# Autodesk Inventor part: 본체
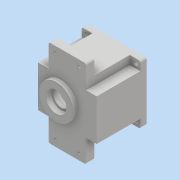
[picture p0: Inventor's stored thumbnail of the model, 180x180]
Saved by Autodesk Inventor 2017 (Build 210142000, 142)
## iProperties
Part Number: 본체
Material: 일반
Document SubType Name: Modeling
Designer: user
Density: 1 g/cm^3
Appearance: 기본값
Mass: 324.576 g
Surface Area: 793.925 cm^2
Volume: 324.576 cm^3
Author: user
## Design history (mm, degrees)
sketch "스케치1"
  geometry: L1 (-30, 70)-(30, 70); L2 (30, -70)-(-30, -70); L3 (-30, 70)-(30, -70); L4 (30, 70)-(-30, -70); L5 (47, 33)-(47, -33); L6 (-47, -33)-(-47, 33); L7 (-47, 33)-(47, -33); L8 (47, 33)-(-47, -33); L9 (30, 70)-(30, 33); L10 (30, -33)-(30, -70); L11 (-47, 33)-(-30, 33); L12 (30, 33)-(47, 33); L13 (-30, -70)-(-30, -33); L14 (-30, 33)-(-30, 70); L15 (47, -33)-(30, -33); L16 (-30, -33)-(-47, -33); 1 further point
  constraints: 32 end point, 10 parallel, 4 midpoint, 4 perpendicular, 3 horizontal
  dimensions: "d6" = 60 distance of L2.start L2.end; "d7" = 140 distance of L1.end L2.start; "d8" = 94 distance of L5.end L6.start; "d9" = 66 distance of L5.start L5.end; "d10" = 60 distance of L1.start L1.end; "d11" = 66 distance of L6.start L6.end; "d12" = 37 distance of L11.end L1.start; "d13" = 37 distance of L2.end L13.end
extrude "돌출1" new body sketch "스케치1" distance "d14" = 13; taper "d15" = 0 deg
sketch "스케치2"
  geometry: L1 (-30, 33)-(-30, 70) reference; L2 (30, -33)-(47, -33) reference; L3 (47, 33)-(47, -33); L4 (-47, -33)-(-47, 33); L5 (-47, 33)-(47, -33); L6 (47, 33)-(-47, -33); L7 (30, -70)-(30, -33) reference; L8 (-30, 47)-(30, 47); L9 (30, -47)-(-30, -47); L10 (-30, 47)-(30, -47); L11 (30, 47)-(-30, -47); L12 (30, 47)-(30, 33); L13 (30, -33)-(30, -47); L14 (-47, 33)-(-30, 33); L15 (30, 33)-(47, 33); L16 (47, -33)-(30, -33); L17 (-30, -33)-(-47, -33); L18 (-30, -47)-(-30, -33); L19 (-30, 33)-(-30, 47); 1 further point
  constraints: 32 end point, 10 parallel, 4 midpoint, 4 perpendicular, 3 horizontal, 1 point on line
  dimensions: "d31" = 94 distance of L8.end L9.start; "d32" = 60 distance of L8.start L8.end; "d33" = 66 distance of L4.start L4.end; "d34" = 60 distance of L9.start L9.end; "d35" = 17 distance of L4.end L14.end
extrude "돌출2" join sketch "스케치2" distance "d16" = 57; taper "d17" = 0 deg
sketch "스케치3"
  geometry: L1 (47, -47)-(-47, -47); L2 (-47, -47)-(-47, 47); L3 (-47, 47)-(47, 47); L4 (47, 47)-(47, -47); L5 (47, -47)-(-47, 47); L6 (-47, -47)-(47, 47); 1 further point
  constraints: 12 end point, 2 midpoint, 2 parallel, 1 horizontal, 1 perpendicular
  dimensions: "d18" = 94 distance of L2.end L3.end; "d19" = 94 distance of L1.end L2.end
extrude "돌출3" join sketch "스케치3" distance "d20" = 10; taper "d21" = 0 deg
sketch "스케치4"
  geometry: C1 r 43 at (0, 0); 1 further point
  constraints: 1 centre point, 1 coincident
  dimensions: "d22" = 86 diameter of C1
extrude "돌출4" cut sketch "스케치4" distance "d23" = 9; taper "d24" = 0 deg
sketch "스케치5"
  geometry: C1 r 40 at (0, 0); 1 further point
  constraints: 1 centre point, 1 coincident
  dimensions: "d30" = 80 diameter of C1
extrude "돌출5" cut sketch "스케치5" distance "d36" = 62; taper "d37" = 0 deg
sketch "스케치6"
  geometry: L1 (3.994, -35.778)-(3.994, -39.8); L2 (3.994, -35.778)-(8.016, -35.778); L3 (-3.994, -35.778)-(-3.994, -39.8); L4 (-3.994, -35.778)-(0.029, -35.778); L5 (-3.994, 35.778)-(-3.994, 36.333); L6 (-3.994, 35.778)-(-3.439, 35.778); L7 (3.994, 35.778)-(3.994, 36.333); L8 (3.994, 35.778)-(4.549, 35.778); A1 r 36 centre (0, 0) between (0, -36) and (0, 36); A2 r 4 centre (0, -36) between (3.994, -35.778) and (-3.994, -35.778); A3 r 4 centre (0, 36) between (-3.994, 36.222) and (3.994, 36.222); A4 r 40 centre (0, 0) between (-3.994, 39.8) and (3.994, 39.8) reference; A5 r 40 centre (0, 0) between (-7.561, 39.279) and (7.561, 39.279); A6 r 3 centre (-6.994, 36.333) between (-3.994, 36.333) and (-7.561, 39.279); A7 r 3 centre (6.994, 36.333) between (7.561, 39.279) and (3.994, 36.333); 1 further point
  constraints: 24 point on circle, 16 end point, 6 centre point, 4 horizontal, 4 perpendicular, 4 point on line, 4 tangent, 2 coincident, 2 equal radius, 2 vertical alignment
  dimensions: "d38" = 72 diameter of A1; "d95" = 8 diameter of A3; "d96" = 8 diameter of A2; "d97" = 90 deg angle of L1 L2; "d98" = 90 deg angle of L3 L4; "d99" = 90 deg angle of L6 L5; "d100" = 90 deg angle of L8 L7; "d101" = 3 radius of A6 (derived)
sketch "스케치14"
  geometry: L1 (0, 0)-(-11, 0); L2 (0, 0)-(20, 0); A1 r 21 centre (-11, 0) between (7.984, 8.978) and (7.984, -8.978); A2 r 15 centre (20, 0) between (7.984, -8.978) and (7.984, 8.978)
  constraints: 4 end point, 4 point on circle, 2 centre point, 2 coincident, 2 horizontal
  dimensions: "d60" = 11 distance of L1.start L1.end; "d62" = 20 distance of L1.start L2.end; "d63" = 42 diameter of A1; "d64" = 30 diameter of A2
extrude "돌출12" join sketch "스케치14" distance "d65" = 7; taper "d66" = 0 deg
sketch "스케치15"
  geometry: C1 r 17.5 at (-11, 0); A1 r 21 centre (-11, 0) between (7.984, 8.978) and (7.984, -8.978) reference; 1 further point
  constraints: 1 centre point, 1 coincident
  dimensions: "d67" = 35 diameter of C1
extrude "돌출13" cut sketch "스케치15" distance "d68" = 10; taper "d69" = 0 deg
sketch "스케치16"
  geometry: C1 r 17.5 at (0, 0) reference; C2 r 12.5 at (0, 0); 1 further point
  constraints: 1 centre point, 1 coincident
  dimensions: "d70" = 25 diameter of C2
extrude "돌출14" cut sketch "스케치16" distance "d71" = 4.7; taper "d72" = 0 deg
sketch "스케치18"
  geometry: C1 r 27.5 at (-11, 0); 2 further points
  constraints: 1 centre point, 1 coincident
  dimensions: "d73" = 55 diameter of C1
extrude "돌출15" join sketch "스케치18" distance "d74" = 7; taper "d75" = 0 deg
sketch "스케치19"
  geometry: C1 r 27.5 at (0, 0) reference; C2 r 16 at (0, 0); 1 further point
  constraints: 1 centre point, 1 coincident
  dimensions: "d76" = 32 diameter of C2
extrude "돌출16" cut sketch "스케치19" distance "d77" = 8.3; taper "d78" = 0 deg
sketch "스케치20"
  geometry: C1 r 11 at (20, 0); A1 r 15 centre (20, 0) between (7.984, -8.978) and (7.984, 8.978) reference; 1 further point
  constraints: 1 centre point, 1 coincident
  dimensions: "d79" = 22 diameter of C1
extrude "돌출17" cut sketch "스케치20" distance "d80" = 7; taper "d81" = 0 deg
sketch "스케치21"
  geometry: C1 r 11 at (0, 0) reference; C2 r 9.5 at (0, 0); 1 further point
  constraints: 1 centre point, 1 coincident
  dimensions: "d82" = 19 diameter of C2
extrude "돌출18" cut sketch "스케치21" distance "d83" = 3; taper "d84" = 0 deg
chamfer "모따기1" distance "d86" = 1; stored, may be unused: second distance "d87" = 2, angle "d88" = 45 deg
chamfer "모따기2" distance "d89" = 0.8; stored, may be unused: second distance "d90" = 2, angle "d91" = 30 deg
chamfer "모따기3" distance "d92" = 1; stored, may be unused: second distance "d93" = 2, angle "d94" = 45 deg
extrude "돌출19" join sketch "스케치6" distance "d102" = 62; taper "d103" = 0 deg
sketch "스케치22"
  geometry: A1 r 4 centre (0, -36) between (3.994, -35.778) and (-3.994, -35.778) reference; A2 r 4 centre (0, 36) between (-3.994, 35.778) and (3.994, 35.778) reference; 3 further points
  constraints: 2 coincident
hole "구멍1" sketch "스케치22" at (0, -36), (0, 36) diameter "d104" = 3.242; stored, may be unused: countersink angle "d108" = 90 deg, drill point angle "d110" = 118 deg; dims "d105" = 7, "d106" = 4, "d107" = 2, "d109" = 9
fillet "모깎기2" dims "d111" = 3
sketch "스케치23"
  geometry: L1 (40, -40)-(-40, -40); L2 (-40, -40)-(-40, 40); L3 (-40, 40)-(40, 40); L4 (40, 40)-(40, -40); L5 (40, -40)-(-40, 40); L6 (-40, -40)-(40, 40); 1 further point
  constraints: 12 end point, 2 midpoint, 2 parallel, 1 horizontal, 1 perpendicular
  dimensions: "d112" = 80 distance of L2.end L3.end; "d113" = 80 distance of L1.end L2.end
hole "구멍2" sketch "스케치23" at (-40, 40), (-40, -40), (40, -40), (40, 40) diameter "d114" = 7; stored, may be unused: countersink angle "d118" = 90 deg, drill point angle "d120" = 118 deg; dims "d115" = 7, "d116" = 4, "d117" = 2, "d119" = 9
sketch "스케치24"
  geometry: L1 (19, -60)-(-19, -60); L2 (-19, -60)-(-19, 60); L3 (-19, 60)-(19, 60); L4 (19, 60)-(19, -60); L5 (19, -60)-(-19, 60); L6 (-19, -60)-(19, 60); 1 further point
  constraints: 12 end point, 2 midpoint, 2 parallel, 1 horizontal, 1 perpendicular
  dimensions: "d121" = 38 distance of L2.end L3.end; "d122" = 120 distance of L1.end L2.end
hole "구멍3" sketch "스케치24" at (-19, -60), (19, -60), (19, 60), (-19, 60) diameter "d123" = 10; stored, may be unused: countersink angle "d127" = 90 deg, drill point angle "d129" = 0 deg; dims "d124" = 7, "d125" = 4, "d126" = 2, "d128" = 5
sketch "스케치25"
  geometry: L1 (38, 0)-(0, 0); L2 (0, 0)-(0, -120); L3 (0, -120)-(38, -120); L4 (38, -120)-(38, 0); L5 (38, 0)-(0, -120); L6 (0, 0)-(38, -120); C1 r 5 at (0, -120) reference; 1 further point
  constraints: 12 end point, 2 midpoint, 2 parallel, 1 horizontal, 1 perpendicular
hole "구멍4" sketch "스케치25" at (0, -120), (38, -120), (38, 0), (0, 0) diameter "d130" = 4.5; stored, may be unused: countersink angle "d134" = 90 deg, drill point angle "d136" = 0 deg; dims "d131" = 7, "d132" = 4, "d133" = 2, "d135" = 5
sketch "스케치26"
  geometry: L1 (77, 80)-(-11, 80) reference; L2 (33, 80)-(33, 40); 2 further points
  constraints: 2 end point, 1 coincident, 1 midpoint, 1 vertical, 1 other
  dimensions: "d137" = 40 distance of L2.start L2.end
feature "엠보싱1" sketch "스케치26" dims "d6" = 60, "d7" = 140, "d8" = 94, "d9" = 66, "d10" = 60, "d11" = 66, "d12" = 37, "d13" = 37, "d138" = 0.5, "d139" = 0
fillet "모깎기3" dims "d140" = 3
fillet "모깎기4" dims "d141" = 3
node "솔리드1"
mirror "미러1"
other parameters: "d25" = 72
